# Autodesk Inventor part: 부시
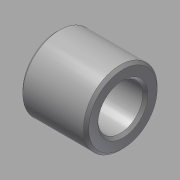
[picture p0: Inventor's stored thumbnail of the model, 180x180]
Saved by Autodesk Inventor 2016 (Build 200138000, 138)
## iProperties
Created: 2016-10
Part Number: 부시
Material: 강철, 연강
Document SubType Name: Modeling
Designer: mduedu
Density: 1 g/cm^3
Appearance: 강철
Author: mduedu
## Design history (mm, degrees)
sketch "스케치1"
  geometry: C1 r 14 at (0, 0); C2 r 8.5 at (0, 0); 1 further point
  constraints: 2 centre point, 2 coincident
  dimensions: "d0" = 28 diameter of C1; "d1" = 17 diameter of C2
extrude "돌출1" new body sketch "스케치1" distance "d2" = 25; taper "d3" = 0 deg
chamfer "모따기1" distance "d4" = 1; stored, may be unused: second distance "d5" = 2, angle "d6" = 45 deg
chamfer "모따기2" distance "d7" = 1; stored, may be unused: second distance "d8" = 2, angle "d9" = 45 deg
node "솔리드1"
